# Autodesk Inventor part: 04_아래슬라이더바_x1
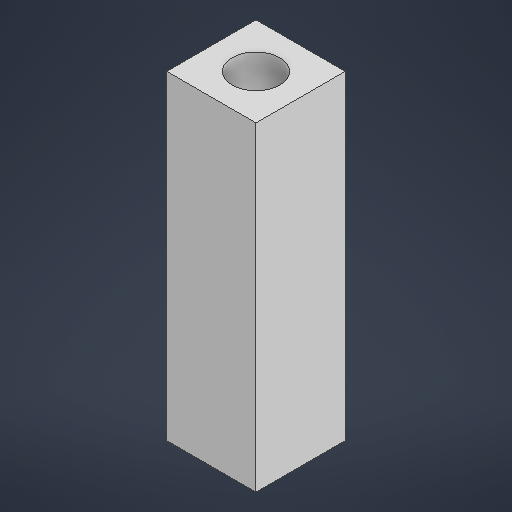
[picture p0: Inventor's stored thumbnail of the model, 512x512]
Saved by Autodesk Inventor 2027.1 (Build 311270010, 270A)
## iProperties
Created: 2026-11
Part Number: 04_아래슬라이더바_x1
Material: Generic
Document SubType Name: Modeling
Designer: djshs
Density: 1 g/cm^3
Appearance: Default
Author: djshs
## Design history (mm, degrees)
sketch "스케치1"
  geometry: L1 (6, 6)-(-6, 6); L2 (-6, 6)-(-6, -6); L3 (-6, -6)-(6, -6); L4 (6, -6)-(6, 6); L5 (6, 6)-(-6, -6); L6 (-6, 6)-(6, -6); C1 r 3.2 at (0, 0); 1 further point
  constraints: 12 end point, 2 midpoint, 2 parallel, 1 centre point, 1 coincident, 1 horizontal, 1 perpendicular
  dimensions: "d0" = 12 distance of L3.end L2.end; "d1" = 12 distance of L2.end L1.end; "d2" = 6.4 diameter of C1
extrude "돌출1" new body sketch "스케치1" distance "d3" = 43; taper "d4" = 0 deg
node "솔리드1"
